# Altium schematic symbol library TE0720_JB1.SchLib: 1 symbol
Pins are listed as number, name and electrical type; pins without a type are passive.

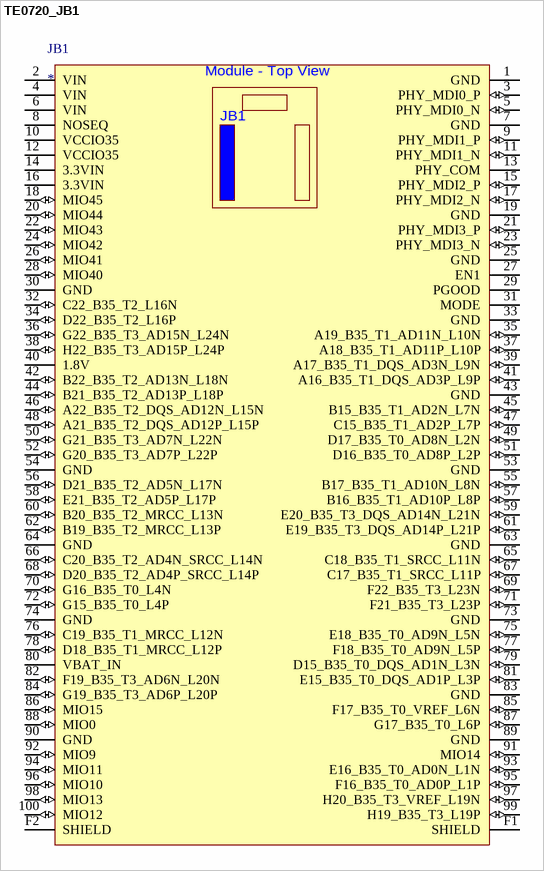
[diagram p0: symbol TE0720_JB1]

## TE0720_JB1
designator JB1
pins: 1 GND (power), 2 VIN (power), 3 PHY_MDI0_P (io), 4 VIN (power), 5 PHY_MDI0_N (io), 6 VIN (power), 7 GND (power), 8 NOSEQ, 9 PHY_MDI1_P (io), 10 VCCIO35 (power), 11 PHY_MDI1_N (io), 12 VCCIO35 (power), 13 PHY_COM, 14 3.3VIN (power), 15 PHY_MDI2_P (io), 16 3.3VIN (power), 17 PHY_MDI2_N (io), 18 MIO45 (io), 19 GND (power), 20 MIO44 (io), 21 PHY_MDI3_P (io), 22 MIO43 (io), 23 PHY_MDI3_N (io), 24 MIO42 (io), 25 GND (power), 26 MIO41 (io), 27 EN1, 28 MIO40 (io), 29 PGOOD, 30 GND (power), 31 MODE, 32 C22_B35_T2_L16N (io), 33 GND (power), 34 D22_B35_T2_L16P (io), 35 A19_B35_T1_AD11N_L10N (io), 36 G22_B35_T3_AD15N_L24N (io), 37 A18_B35_T1_AD11P_L10P (io), 38 H22_B35_T3_AD15P_L24P (io), 39 A17_B35_T1_DQS_AD3N_L9N (io), 40 1.8V (power), 41 A16_B35_T1_DQS_AD3P_L9P (io), 42 B22_B35_T2_AD13N_L18N (io), 43 GND (power), 44 B21_B35_T2_AD13P_L18P (io), 45 B15_B35_T1_AD2N_L7N (io), 46 A22_B35_T2_DQS_AD12N_L15N (io), 47 C15_B35_T1_AD2P_L7P (io), 48 A21_B35_T2_DQS_AD12P_L15P (io), 49 D17_B35_T0_AD8N_L2N (io), 50 G21_B35_T3_AD7N_L22N (io), 51 D16_B35_T0_AD8P_L2P (io), 52 G20_B35_T3_AD7P_L22P (io), 53 GND (power), 54 GND (power), 55 B17_B35_T1_AD10N_L8N (io), 56 D21_B35_T2_AD5N_L17N (io), 57 B16_B35_T1_AD10P_L8P (io), 58 E21_B35_T2_AD5P_L17P (io), 59 E20_B35_T3_DQS_AD14N_L21N (io), 60 B20_B35_T2_MRCC_L13N (io), 61 E19_B35_T3_DQS_AD14P_L21P (io), 62 B19_B35_T2_MRCC_L13P (io), 63 GND (power), 64 GND (power), 65 C18_B35_T1_SRCC_L11N (io), 66 C20_B35_T2_AD4N_SRCC_L14N (io), 67 C17_B35_T1_SRCC_L11P (io), 68 D20_B35_T2_AD4P_SRCC_L14P (io), 69 F22_B35_T3_L23N (io), 70 G16_B35_T0_L4N (io), 71 F21_B35_T3_L23P (io), 72 G15_B35_T0_L4P (io), 73 GND (power), 74 GND (power), 75 E18_B35_T0_AD9N_L5N (io), 76 C19_B35_T1_MRCC_L12N (io), 77 F18_B35_T0_AD9N_L5P (io), 78 D18_B35_T1_MRCC_L12P (io), 79 D15_B35_T0_DQS_AD1N_L3N (io), 80 VBAT_IN (power), 81 E15_B35_T0_DQS_AD1P_L3P (io), 82 F19_B35_T3_AD6N_L20N (io), 83 GND (power), 84 G19_B35_T3_AD6P_L20P (io), 85 F17_B35_T0_VREF_L6N (io), 86 MIO15 (io), 87 G17_B35_T0_L6P (io), 88 MIO0 (io), 89 GND (power), 90 GND (power), 91 MIO14 (io), 92 MIO9 (io), 93 E16_B35_T0_AD0N_L1N (io), 94 MIO11 (io), 95 F16_B35_T0_AD0P_L1P (io), 96 MIO10 (io), 97 H20_B35_T3_VREF_L19N (io), 98 MIO13 (io), 99 H19_B35_T3_L19P (io), 100 MIO12 (io), F1 SHIELD (power), F2 SHIELD (power)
